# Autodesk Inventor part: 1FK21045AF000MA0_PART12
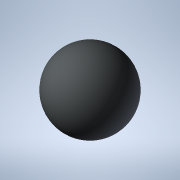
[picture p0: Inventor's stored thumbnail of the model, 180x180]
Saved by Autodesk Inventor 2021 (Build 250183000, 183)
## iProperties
Created: 2025-04
Part Number: 1FK21045AF000MA0_PART12
Material: Generic
Catalog Web Link: www.3dfindit.com
Description: -Servo synchronous motor
Document SubType Name: Modeling
Designer: psAdmin
Mass: 0.137258 g
Surface Area: 1.2868 cm^2
Volume: 0.137258 cm^3
Density: 1 g/cm^3
Appearance: PSOLRGB-212-217-219
Category: PARTsolutions
Title: 1FK21045AF000MA0_PART12
Author: Cadenas PARTsolutions
Comments: Servo synchronous motor
Sending System: PARTsolutions
Preprocessor: ST-DEVELOPER v19.3
PSOL_IDENT_0: {$CADENAS_DATA/23d-libs/siemens_ag/_cat_/8b/0a/1fk21045af000ma0.prj},216 {VTYP=3D},{NB=1FK21045AF000
PSOL_IDENT_1: MA0_PART12},{LINA=1FK21045AF000MA0_PART12},{NN=1FK21045AF000MA0_PART12},{NOPRJ=TRUE},{DATE=19.08.202
PSOL_IDENT_2: 5 14:00:48},{GEOMDATE=30.07.2025 02:00:28},{VERSION=},{LINEID=10},{WBVAR=},{WBNUMERIC=}  {NB=1FK2104
PSOL_IDENT_3: 5AF000MA0_PART12},{LINA=1FK21045AF000MA0_PART12},{KT=DUMMY},{PREVIEW=../../../_pool_/a9/69/p_d211_xx
PSOL_IDENT_4: _00818j.png},{DESCSHORT=SIMOTICS S-1FK2 HD, SINAMICS S210 3AC 400V-480V, 2.4 Nm, 3000 rpm},{DESCLONG=
PSOL_IDENT_5: SIMOTICS S-1FK2 HD servo motor M0=2.4 Nm; PN = 0.75 kW at nN=3000 rpm (380-480 V); PN = 0.375 kW at
PSOL_IDENT_6: nN=1500 rpm (200-240 V); degree of protection IP64; cylindrical shaft D19x40mm; absolute encoder 22-
PSOL_IDENT_7: bit + 12-bit multiturn (encoder AM22DQC); with OCC interface; plug size M17, rotatable; SIMOTICS S-1
PSOL_IDENT_8: FK2 servomotorfor a wide range of uses in industrial environments. SIMOTICS S‑1FK2 servomotors are c
PSOL_IDENT_9: ompact synchronous motors with a high dynamic performance that set themselves apart as a result of t
PSOL_IDENT_10: heir high power density, degree of protection and overload capability. The motors are available in t
PSOL_IDENT_11: wo variants: as High Dynamic variant (highest dynamic performance as a result of the low intrinsic m
PSOL_IDENT_12: oment of inertia for applications demanding a high dynamic performance with low moved masses) - and
PSOL_IDENT_13: as Compact variant (precise and stable closed-loop control for medium up to large moved masses as a
PSOL_IDENT_14: result of a medium intrinsic moment of inertia). SIMOTICSS‑1FK2 servomotors fully exploit their stre
PSOL_IDENT_15: ngths in a system with the SINAMICSS210 frequency converter and simple connection using the one cabl
PSOL_IDENT_16: e connection (OCC). Advantages include the short control and positioning times, fast and precise cor
PSOL_IDENT_17: rection of disturbing quantities as well as stable control with a high dynamic performance. The serv
PSOL_IDENT_18: o motors can be configured to address a wide range of requirements. For example with and without hol
PSOL_IDENT_19: ding brake, IP64 or IP65 degree of protection, singleturn or multiturn absolute encoders - to name j
PSOL_IDENT_20: ust a few. Further, the servomotors are available in different shaft heights extending from 20 to 10
PSOL_IDENT_21: 0. A shaft sealing ring is available to achieve an IP65 degree of protection and for subsequent moun
PSOL_IDENT_22: ting at the motor or as spare part. SIMOTICS - the optimum motor for each and every motion control a
PSOL_IDENT_23: pplication.},{INTNO=195125050112},{SUPPLIERALTNO=1FK2104-5AF00-0MA0},{MANUID=1FK21045AF000MA0},{MANU
PSOL_IDENT_24: NAME=Siemens},{MANUTYPEDESC=Synchronous motor 1FK2-HD 2.4 NM},{AAU732=SIMOTICS},{AAO057=S-1FK2},{AAU
PSOL_IDENT_25: 734=SIMOTICS S-1FK2 HD servo motor M0=2.4 Nm; PN = 0.75 kW at nN=3000 rpm (380-480 V); PN = 0.375 kW
PSOL_IDENT_26: at nN=1500 rpm (200-240 V); degree of protection IP64; cylindrical shaft D19x40mm; absolute encoder
PSOL_IDENT_27: 22-bit + 12-bit multiturn (encoder AM22DQC); with OCC interface; plug size M17, rotatable;},{AAW338=
PSOL_IDENT_28: Synchronous motor 1FK2-HD 2.4 NM},{AAO742=SIMOTICS},{AAO663=4042948692912},{NOCUPEROU=1},{PRICEQUANT
PSOL_IDENT_29: ITY=1},{QUANTITYMIN=1},{QUANTITYINT=1},{CTN=85015100},{COO=DE},{AAO676=1FK2104-5AF00-0MA0},{AAO677=S
PSOL_IDENT_30: iemens AG},{ORDERUNIT=C62},{CONTENTUNIT=C62}
NB: 1FK21045AF000MA0_PART12
NT: Servo synchronous motor
NBSYN: $MANUID._PART12
LINA: 1FK21045AF000MA0_PART12
CATALOG: SIEMENS
PREVIEW: ../../../_pool_/a9/69/p_d211_xx_00818j.png
DESCSHORT: SIMOTICS S-1FK2 HD, SINAMICS S210 3AC 400V-480V, 2.4 Nm, 3000 rpm
DESCLONG: SIMOTICS S-1FK2 HD servo motor M0=2.4 Nm; PN = 0.75 kW at nN=3000 rpm (380-480 V); PN = 0.375 kW at nN=1500 rpm (200-240 V); degree of protection IP64; cylindri
INTNO: 195125050112
SUPPLIERALTNO: 1FK2104-5AF00-0MA0
MANUID: 1FK21045AF000MA0
MANUNAME: Siemens
MANUTYPEDESC: Synchronous motor 1FK2-HD 2.4 NM
AAU732: SIMOTICS
AAO057: S-1FK2
AAU734: SIMOTICS S-1FK2 HD servo motor M0=2.4 Nm; PN = 0.75 kW at nN=3000 rpm (380-480 V); PN = 0.375 kW at nN=1500 rpm (200-240 V); degree of protection IP64; cylindri
AAW338: Synchronous motor 1FK2-HD 2.4 NM
AAO742: SIMOTICS
AAO663: 4042948692912.0
NOCUPEROU: 1
PRICEQUANTITY: 1
QUANTITYMIN: 1
QUANTITYINT: 1
CTN: 85015100
COO: DE
ARTICLENO: 1FK21045AF000MA0_PART12
BOMINFO: 1FK21045AF000MA0_PART12
CREATOR: CADENAS GmbH
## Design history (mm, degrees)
feature "2025_04_17_15_40_42_0766"
body "Solid1"
